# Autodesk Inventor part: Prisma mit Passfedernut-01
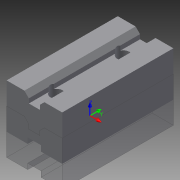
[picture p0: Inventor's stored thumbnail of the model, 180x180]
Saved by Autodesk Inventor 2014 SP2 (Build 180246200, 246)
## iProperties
Created: 2015-06
Part Number: Prisma mit Passfedernut-01
Material: Generisch
Document SubType Name: Modeling
Designer: e_krauts
Density: 1 g/cm^3
Appearance: Vorgabe
Author: e_krauts
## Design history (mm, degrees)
derived "Prisma mit Passfedernut.ipt"
feature "Volumenkörper1::Prisma mit Passfedernut.ipt"
tag "Bezeichnung1"
node "Volumenkörper1"
other parameters: "d7" = 5, "d8" = 4, "d9" = 2, "d10" = 45 deg, "d11" = 25, "d14" = 0, "d17" = 6, "d18" = 2.5, "d20" = 0, "d22" = 2.9, "d24" = 5.5, "d29" = 8, "d30" = 2.25, "d32" = 0, "d33" = 2.9, "d35" = 5.5
